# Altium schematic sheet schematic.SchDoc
size A
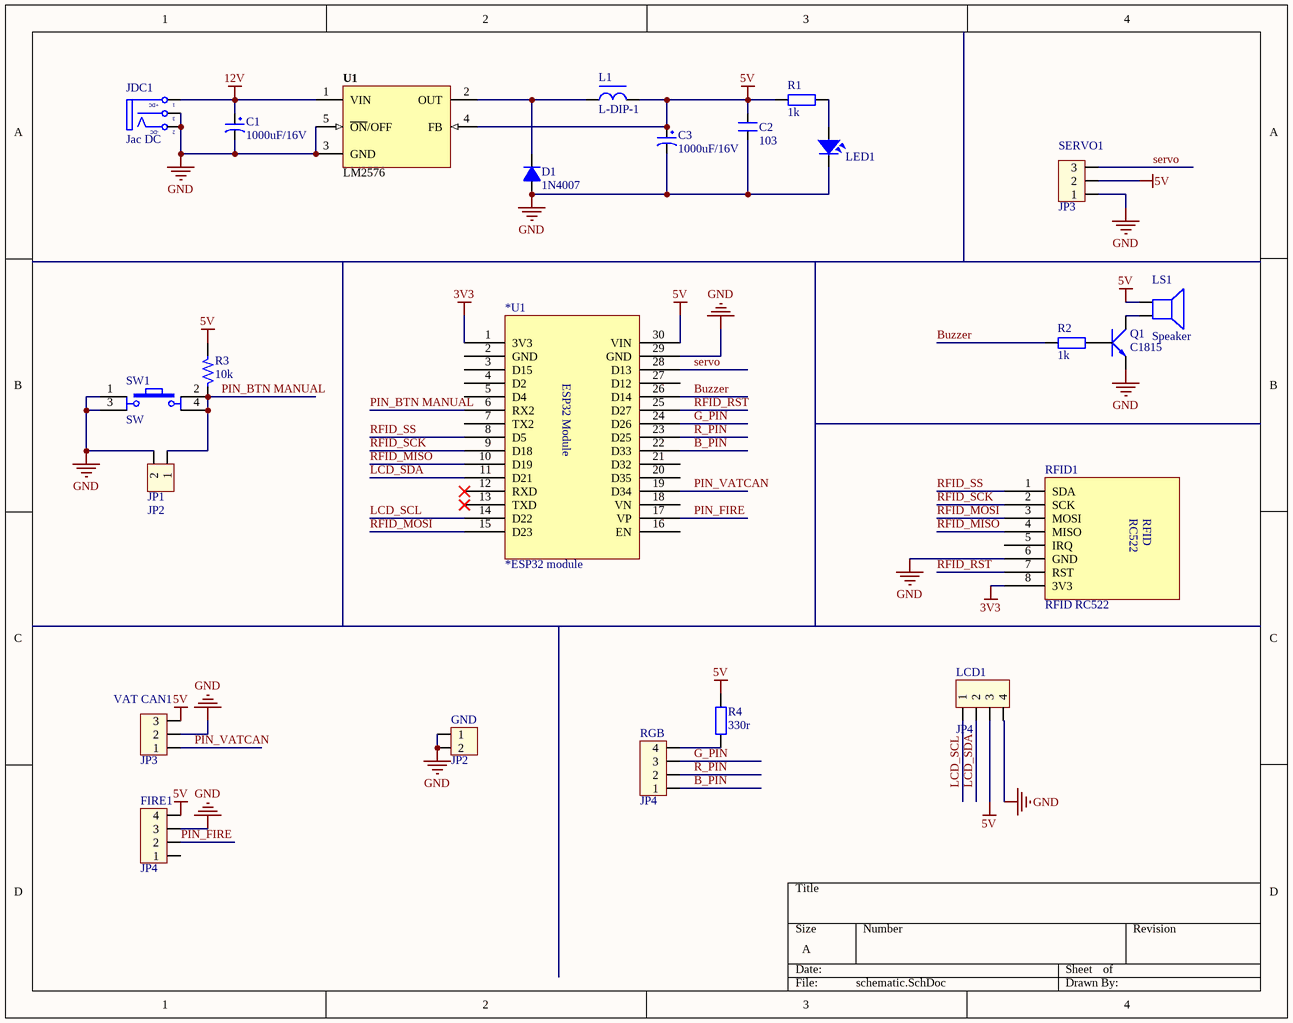
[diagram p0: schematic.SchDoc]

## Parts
*U1  *ESP32 module  [ESP32 Module 30PIN]
C1  1000uF/16V  [CP1.5/3.4]
C2  103  [CN1.5]
C3  1000uF/16V  [CP1.5/3.4]
D1  1N4007  [D1A]
FIRE1  JP4  [CON4]
GND  JP2  [CON2]
JDC1  Jac DC  [DC0]
JP1  JP2  [CON2]
L1  L-DIP-1  [L-DIP-M-9.5x5.5]
LCD1  JP4  [CON4]
LED1  LED  [LED-5-Green]  (value not drawn)
LS1  Speaker  [SPEAKER]
Q1  C1815  [QTO-92]
R1  1k  [R1/4W]
R2  1k  [R1/4W]
R3  10k  [SM-RES-1206]
R4  330r  [R1/4W]
RFID1  RFID RC522  [JP8]
RGB  JP4  [CON4]
SERVO1  JP3  [CON3]
SW1  SW  [SW4]
U1  LM2576  [DIP5-T]
VAT_CAN1  JP3  [CON3]

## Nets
3V3: *U1.1(3V3) RFID1.8(3V3)
5V: *U1.30(VIN) C2.2 C3.1 FIRE1.4 L1.2 LCD1.3 LS1.1 R1.1 R3.2 R4.1 SERVO1.2 U1.4(FB) VAT_CAN1.3
12V: C1.1 JDC1.1(T) U1.1(VIN)
GND: *U1.29(GND) C1.2 C2.1 C3.2 D1.1(A) FIRE1.3 GND.1 GND.2 JDC1.2(TN) JDC1.3(S) JP1.2 LCD1.4 LED1.2 Q1.1(E) RFID1.6(GND) SERVO1.1 SW1.1 SW1.3 U1.3(GND) U1.5(~{ON}/OFF) VAT_CAN1.2
B_PIN: *U1.22(D33) RGB.1
Buzzer: *U1.26(D14) R2.1
G_PIN: *U1.24(D26) RGB.3
LCD_SCL: *U1.14(D22) LCD1.1
LCD_SDA: *U1.11(D21) LCD1.2
PIN_BTN MANUAL: *U1.6(RX2) JP1.1 R3.1 SW1.2 SW1.4
PIN_FIRE: *U1.17(VP) FIRE1.2
PIN_VATCAN: *U1.19(D34) VAT_CAN1.1
R_PIN: *U1.23(D25) RGB.2
RFID_MISO: *U1.10(D19) RFID1.4(MISO)
RFID_MOSI: *U1.15(D23) RFID1.3(MOSI)
RFID_RST: *U1.25(D27) RFID1.7(RST)
RFID_SCK: *U1.9(D18) RFID1.2(SCK)
RFID_SS: *U1.8(D5) RFID1.1(SDA)
servo: *U1.28(D13) SERVO1.3
NetD1_2: D1.2(K) L1.1 U1.2(OUT)
NetLED1_1: LED1.1 R1.2
NetLS1_2: LS1.2 Q1.2(C)
NetQ1_3: Q1.3(B) R2.2
NetR4_2: R4.2 RGB.4

Not connected (* = marked no-connect by the designer): *U1 2(GND) 3(D15) 4(D2) 5(D4) 7(TX2) 12(RXD)* 13(TXD)* 16(EN) 18(VN) 20(D35) 21(D32) 27(D12); FIRE1 1; RFID1 5(IRQ)

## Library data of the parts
*U1 = ESP32 module
C1 C3 = CP4: Cap 1000uF/16V - 220uF/50V; Description 5: 4,7uF>10uF/250V_3,3uF>10uF/400V - 2,2uF>4,7uF/450V; Description 1: 2200uF-3300uF/6,3V - 1000uF-2200uF/10V; Description 2: 1000uF/16V - 470uF => 1000uF/25V - 100uF/100V; Description 3: 330uF>470uF/35V_220uF>470uF/50V_10uF>22uF/250V; Description 4: 220uF => 330uF/63V - 10uF =>33uF/160 - 200V
C2 = CN1.5: Cap np 682pF => 104pF; Value: 0.01uF
D1 = D1A: Diode 1A
FIRE1 LCD1 RGB = Con4: Connector 4
GND JP1 = Con2: Connector 2
JDC1 = DCIN: Jac DC input
L1 = L-DIP-1: Inductor; Value: 150 mH
LED1 = LED: LED Single colour Green and Red; Value: LED 3 ly Single Colour
LS1 = Speaker: Loudspeaker
Q1 = C1815: NPN 600mW, ECB
R1 R2 R4 = R1/4W: Resistor 1/4W; Value: R1/4W - 1K
R3 = R: Resistor 1/4W; Value: R1/4W - 1K
SERVO1 VAT_CAN1 = Con3: Connector 3
SW1 = SW4: Switch button 4 pin; Value: Button chip 4 pin
U1 = LM2576: Max Input Voltage: 12 V; Max Output Current: 3 (6.0 peak) A; Max Output Voltage: mV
